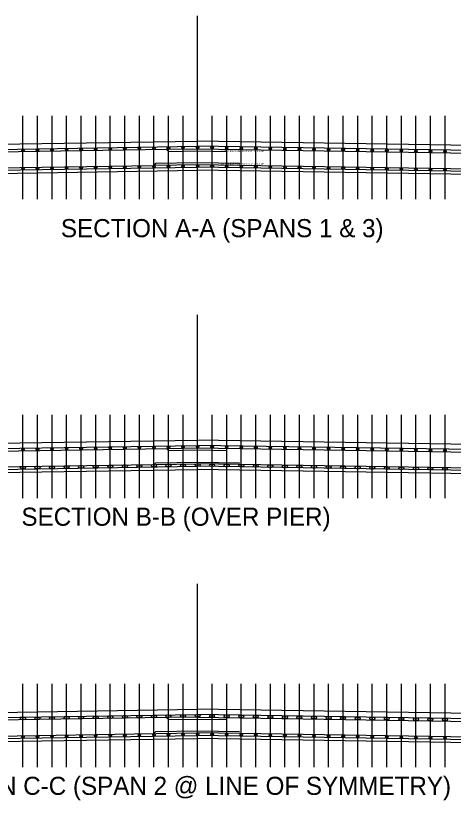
# Model space of a CAD drawing. Extents: x -23.8 to 26.5, y 8.7 to 40.
# Drawn here: x -5.91 to 11.56, y 8.7 to 39.99 of the extents above; entities that cross this region are included whole.
import ezdxf

# ---------------------------------------------------------------- set-up
doc = ezdxf.new("R2010")
doc.units = 0
for name, color, linetype in [('BR_P_Slab_Centerline', 7, 'Continuous'), ('BR_P_Slab_Object', 7, 'Continuous'), ('BR_P_Slab_Reinforcing', 7, 'Continuous'), ('SC_Scratch10', 7, 'Continuous')]:
    doc.layers.add(name, color=color, linetype=linetype)

msp = doc.modelspace()

# ---------------------------------------------------------------- linework, layer by layer
at = {"layer": 'BR_P_Slab_Centerline'}
for p, q in [((1.349, 34.993), (1.349, 39.993)), ((1.349, 23.063), (1.349, 28.063)), ((1.349, 12.329), (1.349, 17.329))]:
    msp.add_line(p, q, dxfattribs=at)
at = {"layer": 'BR_P_Slab_Object'}
for p, q in [((-16.651, 34.712), (1.349, 34.993)), ((19.349, 34.712), (1.349, 34.993)), ((19.349, 34.712), (1.349, 34.993)), ((-16.651, 33.545), (1.349, 33.827)), ((19.349, 33.545), (1.349, 33.827)), ((-16.651, 22.782), (1.349, 23.063)), ((19.349, 22.782), (1.349, 23.063)), ((19.349, 22.782), (1.349, 23.063)), ((-16.651, 21.615), (1.349, 21.897)), ((19.349, 21.615), (1.349, 21.897)), ((-16.651, 12.048), (1.349, 12.329)), ((19.349, 12.048), (1.349, 12.329)), ((19.349, 12.048), (1.349, 12.329)), ((-16.651, 10.881), (1.349, 11.163)), ((19.349, 10.881), (1.349, 11.163))]:
    msp.add_line(p, q, dxfattribs=at)
at = {"layer": 'BR_P_Slab_Reinforcing'}
for p, q in [((-16.681, 34.403), (0.099, 34.665)), ((0.182, 34.583), (0.099, 34.665)), ((0.182, 34.667), (1.348, 34.685)), ((0.182, 34.583), (1.348, 34.601)), ((1.348, 34.685), (19.376, 34.403)), ((1.348, 34.601), (2.515, 34.583)), ((-0.317, 34.109), (1.349, 34.135)), ((1.349, 34.135), (3.016, 34.109)), ((-16.652, 33.77), (-0.402, 34.024)), ((-0.317, 34.109), (-0.402, 34.024)), ((-0.317, 34.025), (1.349, 34.052)), ((1.349, 34.052), (19.35, 33.77)), ((-16.679, 22.473), (0.102, 22.735)), ((0.184, 22.653), (0.102, 22.735)), ((0.184, 22.737), (1.35, 22.755)), ((0.184, 22.653), (1.35, 22.672)), ((1.348, 22.755), (19.376, 22.473)), ((1.348, 22.672), (2.515, 22.653)), ((-16.673, 21.84), (-0.402, 22.095)), ((-0.317, 22.162), (-0.402, 22.078)), ((-0.317, 22.162), (1.349, 22.188)), ((-0.317, 22.096), (1.349, 22.122)), ((1.349, 22.188), (3.016, 22.162)), ((19.371, 21.84), (1.349, 22.122)), ((0.1, 12), (-16.533, 11.739)), ((0.183, 11.917), (0.1, 11.999)), ((1.349, 12.019), (0.183, 12.001)), ((0.183, 11.917), (1.349, 11.936)), ((1.349, 12.019), (19.209, 11.74)), ((1.349, 11.936), (2.516, 11.917)), ((-16.652, 11.106), (-0.402, 11.36)), ((-0.317, 11.445), (-0.402, 11.36)), ((-0.317, 11.445), (1.349, 11.471)), ((-0.317, 11.362), (1.349, 11.388)), ((1.349, 11.471), (3.016, 11.445)), ((19.35, 11.106), (1.349, 11.388))]:
    msp.add_line(p, q, dxfattribs=at)
for centre in [(-1.555, 34.689), (-0.974, 34.699), (-0.393, 34.708), (0.187, 34.717), (0.768, 34.726), (1.349, 34.735), (1.93, 34.726), (2.511, 34.717), (3.092, 34.708), (3.673, 34.699), (4.254, 34.689), (-5.621, 34.626), (-5.041, 34.635), (-4.46, 34.644), (-3.879, 34.653), (-3.298, 34.662), (-2.717, 34.671), (-2.136, 34.68), (4.834, 34.68), (5.415, 34.671), (5.996, 34.662), (6.577, 34.653), (7.158, 34.644), (7.739, 34.635), (8.32, 34.626), (8.901, 34.617), (9.482, 34.608), (10.062, 34.599), (10.643, 34.59), (11.224, 34.581), (-5.621, 33.893), (-5.041, 33.902), (-4.46, 33.911), (-3.879, 33.92), (-3.298, 33.929), (-2.717, 33.938), (-2.136, 33.947), (-1.555, 33.956), (-0.974, 33.965), (-0.393, 33.974), (0.187, 33.983), (0.768, 33.992), (1.349, 34.002), (1.93, 33.992), (2.511, 33.983), (3.092, 33.974), (3.673, 33.965), (4.254, 33.956), (4.834, 33.947), (5.415, 33.938), (5.996, 33.929), (6.577, 33.92), (7.158, 33.911), (7.739, 33.902), (8.32, 33.893), (8.901, 33.884), (9.482, 33.874), (10.062, 33.865), (10.643, 33.856), (11.224, 33.847), (0.768, 22.796), (1.349, 22.805), (1.93, 22.796), (-5.621, 22.696), (-5.041, 22.705), (-4.46, 22.714), (-3.879, 22.723), (-3.298, 22.732), (-2.717, 22.741), (-2.136, 22.75), (-1.555, 22.759), (-0.974, 22.769), (-0.393, 22.778), (0.187, 22.787), (2.511, 22.787), (3.092, 22.778), (3.673, 22.769), (4.254, 22.759), (4.834, 22.75), (5.415, 22.741), (5.996, 22.732), (6.577, 22.723), (7.158, 22.714), (7.739, 22.705), (8.32, 22.696), (8.901, 22.687), (9.482, 22.678), (10.062, 22.669), (10.643, 22.66), (11.224, 22.651), (-5.671, 21.962), (-5.571, 21.962), (-5.091, 21.971), (-4.991, 21.971), (-4.51, 21.98), (-4.41, 21.98), (-3.929, 21.989), (-3.829, 21.989), (-3.348, 21.998), (-3.248, 21.998), (-2.767, 22.007), (-2.667, 22.007), (-2.186, 22.016), (-2.086, 22.016), (-1.605, 22.025), (-1.505, 22.025), (-1.024, 22.034), (-0.924, 22.034), (-0.443, 22.044), (-0.343, 22.044), (0.137, 22.053), (0.237, 22.053), (0.718, 22.062), (0.818, 22.062), (1.299, 22.071), (1.399, 22.071), (1.88, 22.062), (1.98, 22.062), (2.461, 22.053), (2.561, 22.053), (3.042, 22.044), (3.142, 22.044), (3.623, 22.034), (3.723, 22.034), (4.204, 22.025), (4.304, 22.025), (4.784, 22.016), (4.884, 22.016), (5.365, 22.007), (5.465, 22.007), (5.946, 21.998), (6.046, 21.998), (6.527, 21.989), (6.627, 21.989), (7.108, 21.98), (7.208, 21.98), (7.689, 21.971), (7.789, 21.971), (8.27, 21.962), (8.37, 21.962), (8.851, 21.953), (8.951, 21.953), (9.432, 21.944), (9.532, 21.944), (10.012, 21.935), (10.112, 21.935), (10.593, 21.926), (10.693, 21.926), (11.174, 21.916), (11.274, 21.916), (-5.671, 11.962), (-5.571, 11.962), (-5.091, 11.971), (-4.991, 11.971), (-4.51, 11.98), (-4.41, 11.98), (-3.929, 11.989), (-3.829, 11.989), (-3.348, 11.998), (-3.248, 11.998), (-2.767, 12.007), (-2.667, 12.007), (-2.186, 12.016), (-2.086, 12.016), (-1.605, 12.025), (-1.505, 12.025), (-1.024, 12.035), (-0.924, 12.035), (-0.443, 12.044), (-0.343, 12.044), (0.137, 12.053), (0.237, 12.053), (0.718, 12.062), (0.818, 12.062), (1.299, 12.071), (1.399, 12.071), (1.88, 12.062), (1.98, 12.062), (2.461, 12.053), (2.561, 12.053), (3.042, 12.044), (3.142, 12.044), (3.623, 12.035), (3.723, 12.035), (4.204, 12.025), (4.304, 12.025), (4.784, 12.016), (4.884, 12.016), (5.365, 12.007), (5.465, 12.007), (5.946, 11.998), (6.046, 11.998), (6.527, 11.989), (6.627, 11.989), (7.108, 11.98), (7.208, 11.98), (7.689, 11.971), (7.789, 11.971), (8.27, 11.962), (8.37, 11.962), (8.851, 11.953), (8.951, 11.953), (9.432, 11.944), (9.532, 11.944), (10.012, 11.935), (10.112, 11.935), (10.593, 11.926), (10.693, 11.926), (11.174, 11.917), (11.274, 11.917), (-5.621, 11.229), (-5.041, 11.238), (-4.46, 11.247), (-3.879, 11.256), (-3.298, 11.265), (-2.717, 11.274), (-2.136, 11.283), (-1.555, 11.292), (-0.974, 11.301), (-0.393, 11.31), (0.187, 11.319), (0.768, 11.329), (1.349, 11.338), (1.93, 11.329), (2.511, 11.319), (3.092, 11.31), (3.673, 11.301), (4.254, 11.292), (4.834, 11.283), (5.415, 11.274), (5.996, 11.265), (6.577, 11.256), (7.158, 11.247), (7.739, 11.238), (8.32, 11.229), (8.901, 11.22), (9.482, 11.211), (10.062, 11.201), (10.643, 11.192), (11.224, 11.183)]:
    msp.add_circle(centre, 0.05, dxfattribs=at)
at = {"layer": 'SC_Scratch10'}
for p, q in [((-5.621, 32.681), (-5.621, 36.004)), ((-5.041, 32.681), (-5.041, 36.004)), ((-4.46, 32.681), (-4.46, 36.004)), ((-3.879, 32.681), (-3.879, 36.004)), ((-3.298, 32.681), (-3.298, 36.004)), ((-2.717, 32.681), (-2.717, 36.004)), ((-2.136, 32.681), (-2.136, 36.004)), ((-1.555, 32.681), (-1.555, 36.004)), ((-0.974, 32.681), (-0.974, 36.004)), ((-0.393, 32.681), (-0.393, 36.004)), ((0.187, 32.681), (0.187, 36.004)), ((0.768, 32.681), (0.768, 36.004)), ((1.349, 32.681), (1.349, 36.004)), ((1.93, 32.681), (1.93, 36.004)), ((2.511, 32.681), (2.511, 36.004)), ((3.092, 32.681), (3.092, 36.004)), ((3.673, 32.681), (3.673, 36.004)), ((4.254, 32.681), (4.254, 36.004)), ((4.834, 32.681), (4.834, 36.004)), ((5.415, 32.681), (5.415, 36.004)), ((5.996, 32.681), (5.996, 36.004)), ((6.577, 32.681), (6.577, 36.004)), ((7.158, 32.681), (7.158, 36.004)), ((7.739, 32.681), (7.739, 36.004)), ((8.32, 32.681), (8.32, 36.004)), ((8.901, 32.681), (8.901, 36.004)), ((9.482, 32.681), (9.482, 36.004)), ((10.062, 32.681), (10.062, 36.004)), ((10.643, 32.681), (10.643, 36.004)), ((11.224, 32.681), (11.224, 36.004)), ((-16.649, 34.504), (1.349, 34.785)), ((19.348, 34.504), (1.349, 34.785)), ((-16.652, 33.67), (1.349, 33.952)), ((19.35, 33.67), (1.349, 33.952)), ((-5.621, 20.751), (-5.621, 24.075)), ((-5.041, 20.751), (-5.041, 24.075)), ((-4.46, 20.751), (-4.46, 24.075)), ((-3.879, 20.751), (-3.879, 24.075)), ((-3.298, 20.751), (-3.298, 24.075)), ((-2.717, 20.751), (-2.717, 24.075)), ((-2.136, 20.751), (-2.136, 24.075)), ((-1.555, 20.751), (-1.555, 24.075)), ((-0.974, 20.751), (-0.974, 24.075)), ((-0.393, 20.751), (-0.393, 24.075)), ((0.187, 20.751), (0.187, 24.075)), ((0.768, 20.751), (0.768, 24.075)), ((1.349, 20.751), (1.349, 24.075)), ((1.93, 20.751), (1.93, 24.075)), ((2.511, 20.751), (2.511, 24.075)), ((3.092, 20.751), (3.092, 24.075)), ((3.673, 20.751), (3.673, 24.075)), ((4.254, 20.751), (4.254, 24.075)), ((4.834, 20.751), (4.834, 24.075)), ((5.415, 20.751), (5.415, 24.075)), ((5.996, 20.751), (5.996, 24.075)), ((6.577, 20.751), (6.577, 24.075)), ((7.158, 20.751), (7.158, 24.075)), ((7.739, 20.751), (7.739, 24.075)), ((8.32, 20.751), (8.32, 24.075)), ((8.901, 20.751), (8.901, 24.075)), ((9.482, 20.751), (9.482, 24.075)), ((10.062, 20.751), (10.062, 24.075)), ((10.643, 20.751), (10.643, 24.075)), ((11.224, 20.751), (11.224, 24.075)), ((-16.649, 22.574), (1.349, 22.855)), ((19.348, 22.574), (1.349, 22.855)), ((-16.652, 21.74), (1.349, 22.022)), ((19.35, 21.74), (1.349, 22.022)), ((-5.621, 10.017), (-5.621, 13.341)), ((-5.041, 10.017), (-5.041, 13.341)), ((-4.46, 10.017), (-4.46, 13.341)), ((-3.879, 10.017), (-3.879, 13.341)), ((-3.298, 10.017), (-3.298, 13.341)), ((-2.717, 10.017), (-2.717, 13.341)), ((-2.136, 10.017), (-2.136, 13.341)), ((-1.555, 10.017), (-1.555, 13.341)), ((-0.974, 10.017), (-0.974, 13.341)), ((-0.393, 10.017), (-0.393, 13.341)), ((0.187, 10.017), (0.187, 13.341)), ((0.768, 10.017), (0.768, 13.341)), ((1.349, 10.017), (1.349, 13.341)), ((1.93, 10.017), (1.93, 13.341)), ((2.511, 10.017), (2.511, 13.341)), ((3.092, 10.017), (3.092, 13.341)), ((3.673, 10.017), (3.673, 13.341)), ((4.254, 10.017), (4.254, 13.341)), ((4.834, 10.017), (4.834, 13.341)), ((5.415, 10.017), (5.415, 13.341)), ((5.996, 10.017), (5.996, 13.341)), ((6.577, 10.017), (6.577, 13.341)), ((7.158, 10.017), (7.158, 13.341)), ((7.739, 10.017), (7.739, 13.341)), ((8.32, 10.017), (8.32, 13.341)), ((8.901, 10.017), (8.901, 13.341)), ((9.482, 10.017), (9.482, 13.341)), ((10.062, 10.017), (10.062, 13.341)), ((10.643, 10.017), (10.643, 13.341)), ((11.224, 10.017), (11.224, 13.341)), ((-16.649, 11.84), (1.349, 12.121)), ((19.348, 11.84), (1.349, 12.121)), ((-16.652, 11.006), (1.349, 11.288)), ((19.35, 11.006), (1.349, 11.288))]:
    msp.add_line(p, q, dxfattribs=at)

# ---------------------------------------------------------------- texts
for s, height, p in [('#4 TRANSVERSE BAR: 2\'-4" MIN. LAP', 0.07083, (2.284, 34.559)), ('#6 TRANSVERSE BAR: 3\'-4" MIN. LAP', 0.07083, (2.284, 34.049)), ('SECTION A-A (SPANS 1 & 3)', 0.72216, (-4.107, 31.159)), ('SECTION B-B (OVER PIER)', 0.72216, (-5.682, 19.65)), ('SECTION C-C (SPAN 2 @ LINE OF SYMMETRY)', 0.72216, (-10.172, 8.916))]:
    msp.add_text(s, height=height, dxfattribs=at).set_placement(p)

doc.saveas('drawing.dxf')
